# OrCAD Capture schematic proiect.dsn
size A
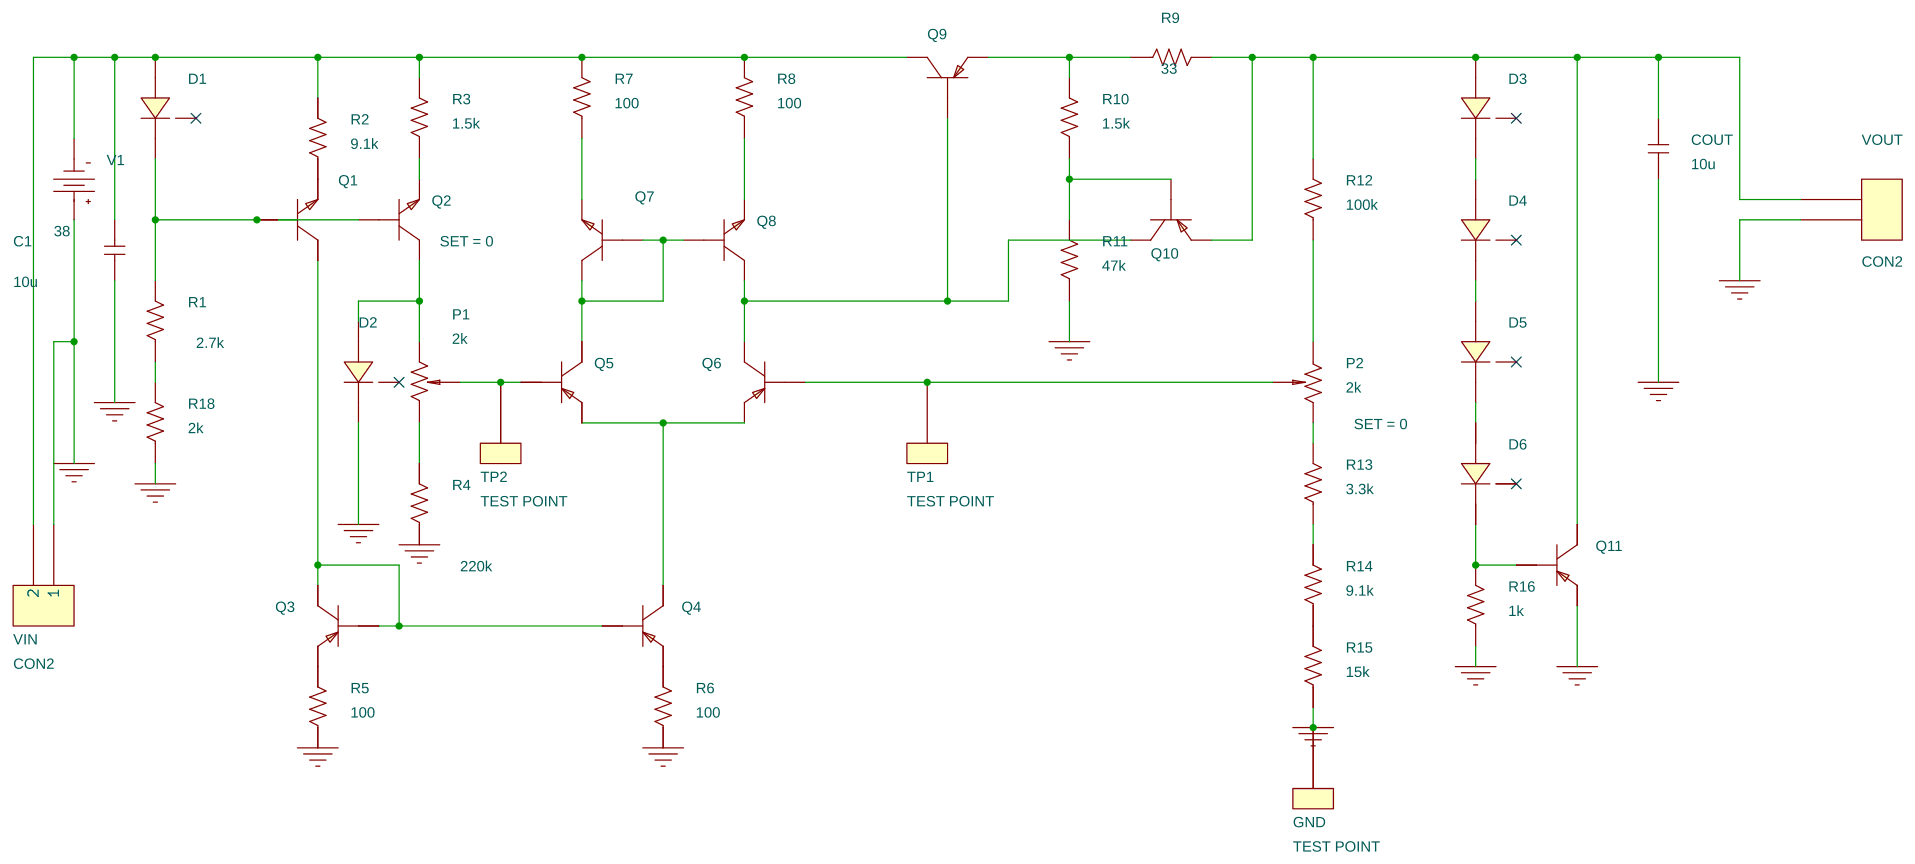
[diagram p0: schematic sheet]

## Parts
C1  10u  [CAPC2008X126N_0805]
COUT  10u  [CAPC2008X126N_0805]
D1  BZX84-C10  [TO236AA]
D2  BZX84-C6V8  [TO236AA]
D3  BZX84-C10  [TO236AA]
D4  BZX84-C10  [TO236AA]
D5  BZX84-C10  [TO236AA]
D6  BZX84-C6V2  [TO236AA]
GND  TEST POINT  [PAD_2X2]
P1  2k  [TS53YL]
P2  2k  [TS53YL]
Q1  QBC817-25  [TO236AA]
Q2  QBC817-25  [TO236AA]
Q3  QBC807-25  [TO236AA]
Q4  QBC807-25  [TO236AA]
Q5  QBC807-25  [TO236AA]
Q6  QBC807-25  [TO236AA]
Q7  QBC817-25  [TO236AA]
Q8  QBC817-25  [TO236AA]
Q9  QMJD32CT4G  [DPACK]
Q10  QBC807-25  [TO236AA]
Q11  QMJD32CT4G  [DPACK]
R1  2.7k  [RES2012X50N_0805]
R2  9.1k  [RES2012X50N_0805]
R3  1.5k  [RES2012X50N_0805]
R4  220k  [RES2012X50N_0805]
R5  100  [RES2012X50N_0805]
R6  100  [RES2012X50N_0805]
R7  100  [RES2012X50N_0805]
R8  100  [RES2012X50N_0805]
R9  33  [RES2012X50N_0805]
R10  1.5k  [RES2012X50N_0805]
R11  47k  [RES2012X50N_0805]
R12  100k  [RES2012X50N_0805]
R13  3.3k  [RES2012X50N_0805]
R14  9.1k  [RES2012X50N_0805]
R15  15k  [RES2012X50N_0805]
R16  1k  [RES2012X50N_0805]
R18  2k  [RES2012X50N_0805]
TP1  TEST POINT  [PAD_2X2]
TP2  TEST POINT  [PAD_2X2]
V1  VDC
VIN  CON2  [CONECTOR]
VOUT  CON2  [CONECTOR]

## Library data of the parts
C1 COUT = C
D1 D3-D5 = BZX84-C10_4
D2 = BZX84-C6V8_3
D6 = BZX84-C6V2_4
GND TP1 TP2 = TEST_POINT
P1 P2 = POT: SET: 0
Q1 Q2 Q7 Q8 = QBC817-25_0
Q3-Q6 Q10 = QBC807-25_0
Q9 Q11 = QMJD32CT4G_0
R1-R16 R18 = R_v2
V1 = VDC: DC: 38
VIN = CON2_2
VOUT = CON2

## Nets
0: C1.1 COUT.1 D2.3(C) GND.1 Q11.3(E) R4.1 R5.1 R6.1 R11.1 R15.1 R16.1 R18.1 V1.0(+) VIN.2(1) VOUT.2
N29620: C1.2 D1.1(A) Q9.2(C) R2.2 R3.2 R7.2 R8.2 V1.1(-) VIN.1(2)
N29692: Q4.3(C) Q5.2(E) Q6.2(E)
N29698: Q5.3(C) Q7.1(B) Q7.3(C) Q8.1(B)
N29704: Q6.3(C) Q8.3(C) Q9.1(B) Q10.3(C)
N29750: Q8.2(E) R8.1
N29762: Q7.2(E) R7.1
N29826: Q9.3(E) R9.1 R10.2
N29912: COUT.2 D3.1(A) Q10.2(E) Q11.2(C) R9.2 R12.2 VOUT.1
N29916: Q10.1(B) R10.1 R11.2
N30052: P2.3(2) R13.2
N30094: D2.1(A) P1.3(2) Q2.3(C)
N30376: D3.3(C) D4.1(A)
N30382: D4.3(C) D5.1(A)
N30508: D6.3(C) Q11.1(B) R16.2
N30716: Q1.3(C) Q3.1(B) Q3.3(C) Q4.1(B)
N35325: R13.1 R14.2
N36428: P2.1 R12.1
N39990: D1.3(C) Q1.1(B) Q2.1(B) R1.2
N42166: D5.3(C) D6.1(A)
N48107: P1.1 R4.2
N55403: P1.2(t) Q5.1(B) TP2.1
N55487: P2.2(t) Q6.1(B) TP1.1
N73496: Q2.2(E) R3.1
N81296: R1.1 R18.2
N83029: R14.1 R15.2
N83031: Q1.2(E) R2.1
N83032: Q3.2(E) R5.2
N83033: Q4.2(E) R6.2

Not connected (* = marked no-connect by the designer): D1 2(NC)*; D2 2(NC)*; D3 2(NC)*; D4 2(NC)*; D5 2(NC)*; D6 2(NC)*
